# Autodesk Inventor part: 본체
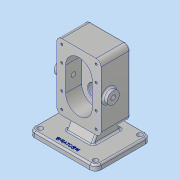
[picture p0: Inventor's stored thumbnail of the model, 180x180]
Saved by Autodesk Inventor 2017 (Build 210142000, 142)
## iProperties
Part Number: 본체
Material: 알루미늄 6061
Document SubType Name: Modeling
Designer: MRC
Density: 2.7 g/cm^3
Appearance: 알루미늄 - 평지
Mass: 1472.54 g
Surface Area: 818.394 cm^2
Volume: 545.387 cm^3
Author: MRC
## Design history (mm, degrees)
sketch "스케치1"
  geometry: L1 (-40, 60)-(40, 60); L2 (40, 60)-(40, -60); L3 (40, -60)-(-40, -60); L4 (-40, -60)-(-40, 60); 3 further points
  constraints: 8 end point, 2 midpoint, 2 parallel, 1 horizontal, 1 horizontal alignment, 1 perpendicular, 1 vertical alignment
  dimensions: "d0" = 80 distance of L1.start L1.end; "d1" = 120 distance of L3.end L1.start
extrude "돌출1" new body sketch "스케치1" distance "d5" = 14; taper "d7" = 0 deg; dims "d6" = 39, "d8" = 0
sketch "스케치2"
  geometry: L1 (-24, 22)-(-24, -22); L2 (24, 22)-(24, -22); A1 r 24 centre (0, 22) between (24, 22) and (-24, 22); A2 r 24 centre (0, -22) between (-24, -22) and (24, -22); 1 further point
  constraints: 4 end point, 4 point on circle, 2 centre point, 2 tangent, 2 vertical alignment, 1 parallel, 1 vertical
  dimensions: "d9" = 48 diameter of A1; "d10" = 48 diameter of A2; "d11" = 44 distance of A2.centre A1.centre; "d12" = 22 distance of point (0, 0) A1.centre (= 0.5 x d11)
extrude "돌출2" cut sketch "스케치2" distance "d13" = 29; taper "d14" = 0 deg
sketch "스케치3"
  geometry: C1 r 19 at (0, 22); 1 further point
  constraints: 1 centre point, 1 vertical alignment
  dimensions: "d15" = 38 diameter of C1; "d16" = 22 distance of point (0, 0) C1.centre
extrude "돌출3" join sketch "스케치3" distance "d17" = 17; taper "d18" = 0 deg
sketch "스케치4"
  geometry: L1 (-60, -102)-(60, -102); L2 (60, -102)-(60, -112); L3 (60, -112)-(-60, -112); L4 (-60, -112)-(-60, -102); L5 (40, 38)-(-40, 38) reference; 2 further points
  constraints: 8 end point, 2 parallel, 1 horizontal, 1 midpoint, 1 perpendicular, 1 vertical alignment
  dimensions: "d19" = 120 distance of L2.end L3.end; "d20" = 10 distance of L3.end L1.start; "d21" = 150 distance between parallel lines of L3 L5
extrude "돌출4" join sketch "스케치4" distance "d22" = 100; taper "d23" = 0 deg
sketch "스케치6"
  geometry: L1 (22, -56)-(22, -48.7); L2 (22, 14)-(22, -15) reference; L3 (22, -56)-(36.404, -56); L4 (36.404, -56)-(36, -55.3); L5 (36, -55.3)-(36, -48.7); L6 (36, -48.7)-(22, -48.7); L7 (46, -15)-(46, 14) reference; L8 (46, 14)-(60, 14) reference; L9 (60, 14)-(60, -39) reference; L10 (60, -39)-(41, -39) reference; L11 (41, -39)-(41, -56) reference; L12 (41, -56)-(3, -56) reference; L13 (3, -56)-(3, -39) reference; L14 (3, -39)-(-60, -39) reference; L15 (-60, -39)-(-60, 14) reference; L16 (-60, 14)-(-46, 14) reference; L17 (-46, 14)-(-46, -15) reference; L18 (-46, -15)-(46, -15) reference; L19 (-80, 44)-(-80, -56) reference; L20 (-80, -56)-(-90, -56) reference; L21 (-90, -56)-(-90, 44) reference; L22 (-90, 44)-(-80, 44) reference; L23 (46, -15)-(46, 14) reference; L24 (46, 14)-(60, 14) reference; L25 (60, 14)-(60, -39) reference; L26 (60, -39)-(41, -39) reference; L27 (41, -39)-(41, -56) reference; L28 (41, -56)-(3, -56) reference; L29 (3, -56)-(3, -39) reference; L30 (3, -39)-(-60, -39) reference; L31 (-60, -39)-(-60, 14) reference; L32 (-60, 14)-(-46, 14) reference; L33 (-46, 14)-(-46, -15) reference; L34 (-46, -15)-(46, -15) reference; L35 (-80, 44)-(-80, -56) reference; L36 (-80, -56)-(-90, -56) reference; L37 (-90, -56)-(-90, 44) reference; L38 (-90, 44)-(-80, 44) reference; 3 further points
  constraints: 10 end point, 2 collinear, 2 midpoint, 2 perpendicular, 1 horizontal, 1 parallel, 1 vertical alignment
  dimensions: "d25" = 30 deg angle of L5 L4; "d26" = 0.7 vertical distance of L3.end L4.end; "d27" = 7.3 distance between parallel lines of L3 L6; "d28" = 28 diameter of L5 L1
revolve "회전1" sketch "스케치6" stored, may be unused: angle "d29" = 90 deg
sketch "스케치7"
  geometry: C1 r 12.5 at (0, -22); A1 r 24 centre (0, 22) between (24, 22) and (-24, 22) reference; A2 r 24 centre (0, -22) between (-24, -22) and (24, -22) reference; 2 further points
  constraints: 2 coincident, 1 centre point
  dimensions: "d30" = 25 diameter of C1
extrude "돌출5" cut sketch "스케치7" distance "d31" = 15; taper "d32" = 0 deg
hole "구멍1" sketch "스케치7" diameter "d33" = 17; stored, may be unused: countersink angle "d37" = 90 deg, drill point angle "d39" = 118 deg; dims "d34" = 6, "d35" = 25, "d36" = 15, "d38" = 8
chamfer "모따기1" distance "d40" = 1; stored, may be unused: second distance "d41" = 2, angle "d42" = 45 deg
fillet "모깎기1" dims "d43" = 0.5
fillet "모깎기2" dims "d65" = 9
fillet "모깎기3" dims "d68" = 10
sketch "스케치13"
  geometry: L1 (-64.412, 5)-(-80, 14); L2 (-80, -46)-(-80, 34) reference; 2 further points
  constraints: 2 end point, 1 horizontal alignment, 1 point on line
  dimensions: "d69" = 60 deg angle of L2 L1
feature "리브3" sketch "스케치13" dims "d70" = 1, "d71" = 48, "d72" = 0, "d73" = 0, "d74" = 1, "d75" = 1
sketch "스케치14"
  geometry: L1 (-62.487, -28.889)-(-80, -39); L2 (-90, -56)-(-80, -56) reference; L3 (-80, -46)-(-80, 34) reference; 1 further point
  constraints: 2 end point, 1 point on line
  dimensions: "d76" = 17 distance from line of L2 L1.end; "d77" = 60 deg angle of L3 L1
feature "리브4" sketch "스케치14" dims "d78" = 1, "d79" = 48, "d80" = 0, "d81" = 0, "d82" = 1, "d83" = 1
fillet "모깎기4" dims "d84" = 3
fillet "모깎기5" dims "d85" = 3
sketch "스케치15"
  geometry: A1 r 7 centre (100, -87) between (100, -94) and (107, -87) reference; A2 r 7 centre (100, -7) between (107, -7) and (100, 0) reference; A3 r 7 centre (0, -7) between (0, 0) and (-7, -7) reference; A4 r 7 centre (0, -87) between (-7, -87) and (0, -94) reference; 5 further points
  constraints: 4 coincident
hole "구멍2" sketch "스케치15" at (0, -87), (0, -7), (100, -7), (100, -87) diameter "d86" = 9; stored, may be unused: countersink angle "d90" = 90 deg, drill point angle "d92" = 118 deg; dims "d87" = 6, "d88" = 25, "d89" = 15, "d91" = 8
node "작업 평면2"
sketch "스케치17"
  geometry: C1 r 11 at (0, 0); 1 further point
  constraints: 1 centre point, 1 coincident
  dimensions: "d94" = 22 diameter of C1
extrude "돌출7" join sketch "스케치17" distance "d95" = 8; taper "d96" = 0 deg
hole "구멍3" diameter "d99" = 8.376; stored, may be unused: countersink angle "d103" = 90 deg, drill point angle "d105" = 118 deg; dims "d97" = 10, "d98" = 10, "d100" = 20, "d101" = 25, "d102" = 15, "d104" = 27.3
fillet "모깎기6" dims "d106" = 3
sketch "스케치18"
  geometry: A1 r 9 centre (31, 51) between (40, 51) and (31, 60) reference; A2 r 9 centre (-31, 51) between (-31, 60) and (-40, 51) reference; 3 further points
  constraints: 2 coincident
hole "구멍4" sketch "스케치18" at (-31, 51), (31, 51) diameter "d107" = 4.134; stored, may be unused: countersink angle "d111" = 90 deg, drill point angle "d113" = 118 deg; dims "d108" = 10, "d109" = 25, "d110" = 15, "d112" = 12
sketch "스케치19"
  geometry: L1 (-10, -7)-(-10, -87) reference; L2 (0, -97)-(100, -97) reference; 2 further points
  constraints: 1 other
  dimensions: "d117" = 60 distance from line of L1 point (50, -87); "d118" = 10 distance from line of L2 point (50, -87)
feature "엠보싱1" sketch "스케치19" dims "d0" = 80, "d1" = 120, "d119" = 0.5, "d120" = 0
node "솔리드1"
mirror "미러1"
pattern_linear "직사각형 패턴1" dims "d116" = 29
mirror "미러2"
node "절단 모서리 투영1"
node "절단 모서리 투영2"
